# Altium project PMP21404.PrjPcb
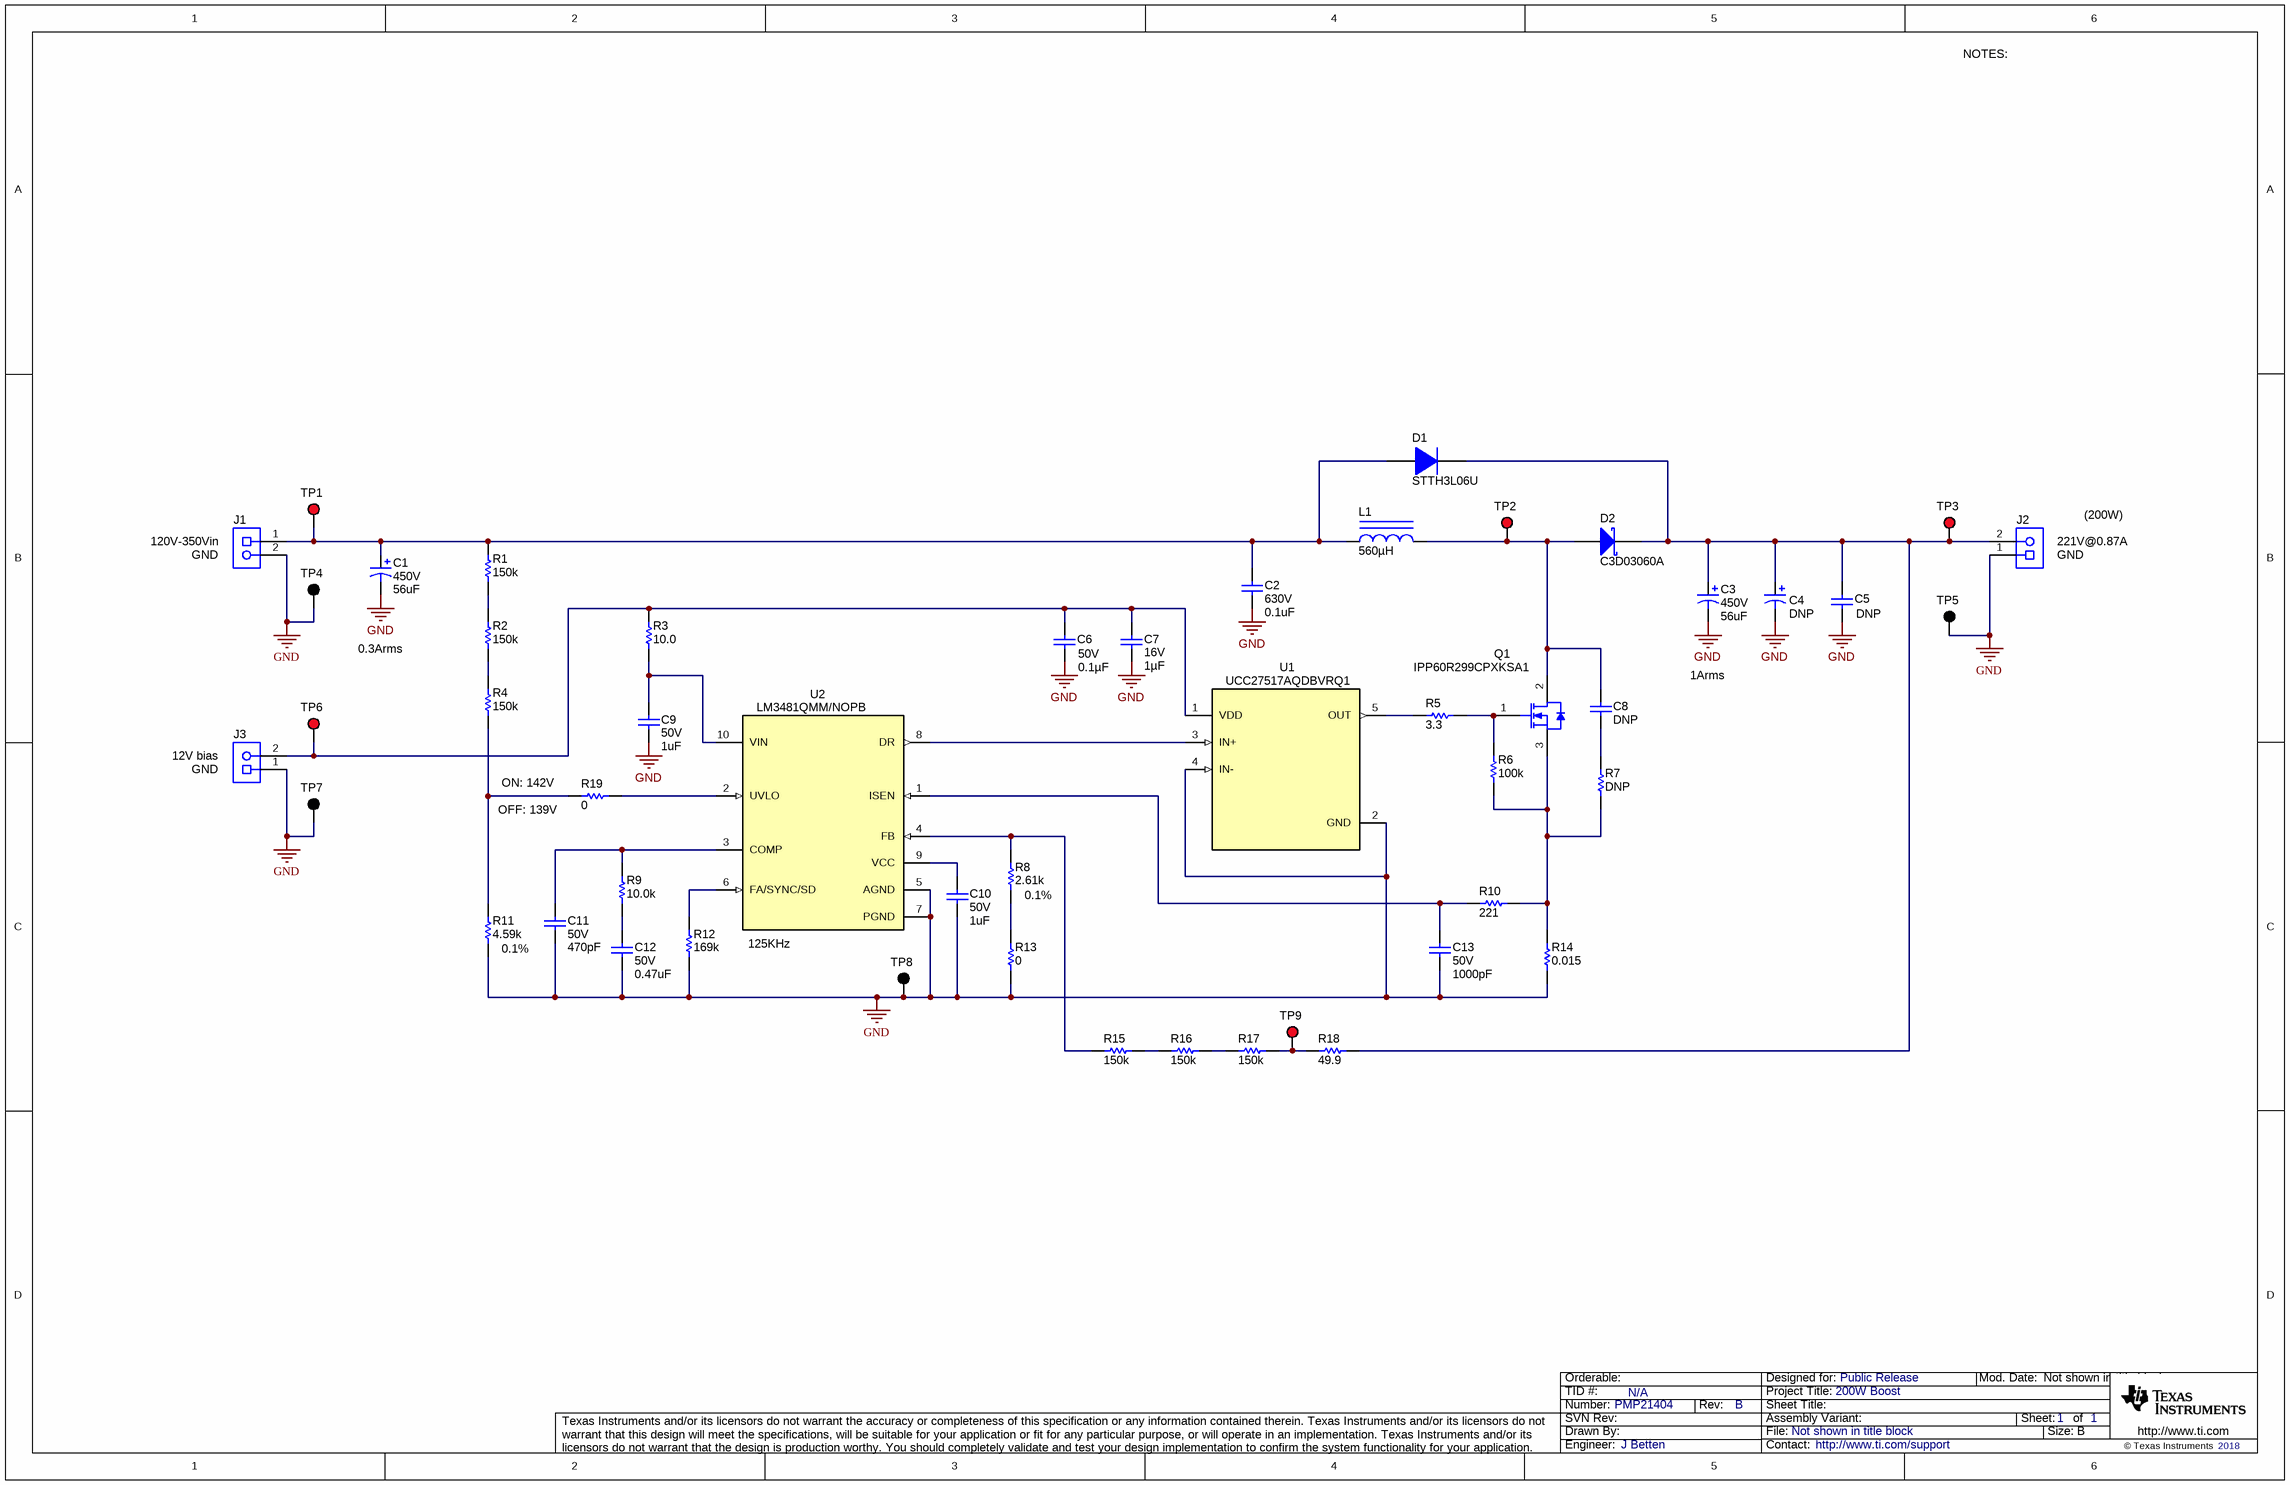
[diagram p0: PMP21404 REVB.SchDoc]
CopyrightYear: 2018; PCB_Layout: J Betten; PCB_Rev: B; PRJ_Customer: Public Release; PRJ_Engineer: J Betten; PRJ_Number: PMP21404; PRJ_Title: 200W Boost; SCH_Rev: B; TechSupport: http://www.ti.com/support; TID: N/A
1 sheet, 50 parts. Net scope: global (net labels, ports and power ports of the same name join across sheets).
Board file: PMP21404 REVB.PcbDoc

## Sheet PMP21404 REVB.SchDoc
size 431 x 279 mm; Date: Not shown in title block; ApprovedBy: Not shown in title block; CheckedBy: Not shown in title block; Author: Not shown in title block; CompanyName: Not shown in title block; Engineer: Not shown in title block; Organization: Not shown in title block; Address1: Not shown in title block; Address2: Not shown in title block; Address3: Not shown in title block; Address4: Not shown in title block; DocumentNumber: 1; Revision: Use project parameter SCH_Rev; SheetNumber: 1; SheetTotal: 1; PageSetup: Record=PageOptions¦CenterHorizontal=True¦CenterVertical=True¦PrintScale=1.00¦XCorrection=1.00¦YCorrection=1.00¦PrintKind=0¦BorderSize=5000000¦LeftOffset=0¦BottomOffset=0¦Orientation=2¦PaperLength=1000¦PaperWidth=1000¦Scale=100¦PaperSource=15¦PrintQuality=600¦MediaType=1¦DitherType=10¦PaperKind=Letter¦PrintScaleMode=1

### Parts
C1  VDC_V: 450V  ValueDisplayed: 56uF  [Nichicon_2000x2500_Snap]  (hidden comment: LLS2W560MELY)
C2  VDC_V: 630V  ValueDisplayed: 0.1uF  [1210_200]  (hidden comment: CGA6L1X7T2J104K160AC)
C3  VDC_V: 450V  ValueDisplayed: 56uF  [Nichicon_2000x2500_Snap]  (hidden comment: LLS2W560MELY)
C4  ValueDisplayed: DNP  [Nichicon_2000x2500_Snap]
C5  ValueDisplayed: DNP  [1210_200]  (hidden comment: CGA6L1X7T2J104K160AC)
C6  VDC_V: 50V  ValueDisplayed: 0.1µF  [0603]  (hidden comment: C0603C104K5RACAUTO)
C7  VDC_V: 16V  ValueDisplayed: 1µF  [0603]  (hidden comment: CGA3E1X7R1C105K080AC)
C8  ValueDisplayed: DNP  [1206_190]  (hidden comment: C3216C0G2E153J160AA)
C9  VDC_V: 50V  ValueDisplayed: 1uF  [0805_HV]  (hidden comment: CGA4J3X7R1H105K125AB)
C10  VDC_V: 50V  ValueDisplayed: 1uF  [0805_HV]  (hidden comment: CGA4J3X7R1H105K125AB)
C11  VDC_V: 50V  ValueDisplayed: 470pF  [0603]  (hidden comment: GRM188R71H471KA01D)
C12  VDC_V: 50V  ValueDisplayed: 0.47uF  [0603]  (hidden comment: CGA3E3X7R1H474K080AB)
C13  VDC_V: 50V  ValueDisplayed: 1000pF  [0603]  (hidden comment: GRM188R71H102JA01D)
D1  STTH3L06U  [SMB]
D2  C3D03060A  [TO-220-2]
J1  Receptacle_2x1  [TERM_BLK_ED555-2DS]  (value not drawn)
J2  Receptacle_2x1  [TERM_BLK_ED555-2DS]  (value not drawn)
J3  Receptacle_2x1  [TERM_BLK_ED555-2DS]  (value not drawn)
L1  ValueDisplayed: 560µH  [Renco_RL1256-3_Pitch_750]  (hidden comment: RL-1256-3-470)
Q1  IPP60R299CPXKSA1  [TO-220AB]
R1  ValueDisplayed: 150k  [1206]  (hidden comment: CRCW1206150KFKEA)
R2  ValueDisplayed: 150k  [1206]  (hidden comment: CRCW1206150KFKEA)
R3  ValueDisplayed: 10.0  [0603]  (hidden comment: CRCW060310R0FKEA)
R4  ValueDisplayed: 150k  [1206]  (hidden comment: CRCW1206150KFKEA)
R5  ValueDisplayed: 3.3  [0603]  (hidden comment: CRCW06033R30JNEA)
R6  ValueDisplayed: 100k  [0603]  (hidden comment: CRCW0603100KFKEA)
R7  ValueDisplayed: DNP  [1206]  (hidden comment: CRCW1206150KFKEA)
R8  Value1: 0.1%  ValueDisplayed: 2.61k  [0603]  (hidden comment: RG1608P-2611-B-T5)
R9  ValueDisplayed: 10.0k  [0603]  (hidden comment: CRCW060310K0FKEA)
R10  value 221  [0603]  (hidden comment: Resistor)
R11  Tolerance_%: 0.1%  ValueDisplayed: 4.59k  [0603]  (hidden comment: RT0603BRD074K59L)
R12  ValueDisplayed: 169k  [0603]  (hidden comment: CRCW0603169KFKEA)
R13  ValueDisplayed: 0  [0603]  (hidden comment: RMCF0603ZT0R00)
R14  ValueDisplayed: 0.015  [1206]  (hidden comment: WSLP1206R0150FEA)
R15  ValueDisplayed: 150k  [1206]  (hidden comment: CRCW1206150KFKEA)
R16  ValueDisplayed: 150k  [1206]  (hidden comment: CRCW1206150KFKEA)
R17  ValueDisplayed: 150k  [1206]  (hidden comment: CRCW1206150KFKEA)
R18  value 49.9  [0603]  (hidden comment: Resistor)
R19  ValueDisplayed: 0  [0603]  (hidden comment: RMCF0603ZT0R00)
TP1  5000  [Keystone5000]  (value not drawn)
TP2  5000  [Keystone5000]  (value not drawn)
TP3  5000  [Keystone5000]  (value not drawn)
TP4  5001  [Keystone5001]  (value not drawn)
TP5  5001  [Keystone5001]  (value not drawn)
TP6  5000  [Keystone5000]  (value not drawn)
TP7  5001  [Keystone5001]  (value not drawn)
TP8  5001  [Keystone5001]  (value not drawn)
TP9  5000  [Keystone5000]  (value not drawn)
U1  UCC27517AQDBVRQ1  [DBV0005A_N]
U2  LM3481QMM/NOPB  [DGS0010A_N]

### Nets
GND: C1.2(-) C2.2 C3.2(-) C4.2(-) C5.2 C6.2 C7.2 C9.2 C10.2 C11.2 C12.2 C13.2 J1.2 J2.1 J3.1 R11.1 R12.1 R13.1 R14.1 TP4.1 TP5.1 TP7.1 TP8.1 U1.2(GND) U1.4(IN-) U2.5(AGND) U2.7(PGND)
NetC1_1: C1.1(+) C2.1 D1.2(A) J1.1 L1.1 R1.2 TP1.1
NetC3_1: C3.1(+) C4.1(+) C5.1 D1.1(K) D2.1(K) J2.2 R18.1 TP3.1
NetC6_1: C6.1 C7.1 J3.2 R3.1 TP6.1 U1.1(VDD)
NetC8_1: C8.1 D2.2(A) L1.2 Q1.2(D) TP2.1
NetC8_2: C8.2 R7.1
NetC9_1: C9.1 R3.2 U2.10(VIN)
NetC10_1: C10.1 U2.9(VCC)
NetC11_1: C11.1 R9.2 U2.3(COMP)
NetC12_1: C12.1 R9.1
NetC13_1: C13.1 R10.2 U2.1(ISEN)
NetQ1_1: Q1.1(G) R5.2 R6.2
NetQ1_3: Q1.3(S) R6.1 R7.2 R10.1 R14.2
NetR1_1: R1.1 R2.2
NetR2_1: R2.1 R4.2
NetR4_1: R4.1 R11.2 R19.2
NetR5_1: R5.1 U1.5(OUT)
NetR8_1: R8.1 R13.2
NetR8_2: R8.2 R15.2 U2.4(FB)
NetR12_2: R12.2 U2.6(FA/SYNC/SD)
NetR15_1: R15.1 R16.2
NetR16_1: R16.1 R17.2
NetR17_1: R17.1 R18.2 TP9.1
NetR19_1: R19.1 U2.2(UVLO)
NetU1_3: U1.3(IN+) U2.8(DR)

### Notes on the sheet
- NOTES:
- (near J1) 120V-350Vin
- (near J1) GND
- (near J2) 221V@0.87A
- (near J2) GND
- (200W)
- 0.3Arms
- 1Arms
- (near J3) 12V bias
- (near J3) GND
- (near R19) ON: 142V
- (near R19) OFF: 139V
- (near U2) 125KHz

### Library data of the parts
C1 C3 = CMP-0010119-2: CAP, AL, 56 uF, 450 V, +/- 20%, TH; Manufacturer: Nichicon; TaMin_C: -25°C; Polarized: Y; SizeAreaWB_mm2: 484; Value1: Unknown; U/M: EA; Value: 56uF; TaMax_C: 85°C; SizeZ_mm: 27; SizeX_mm: 20; Cap_Case: 20x25mm; SizeArea_mm2: 400; CompType: Capacitor; AEC Qualified: N; Cap_F: 56µF; IRMS_A: 6.1dA; AEC Category: Q200
C2 = CMP-0009140-2: CAP, CERM, 0.1 uF, 630 V, +/- 10%, X7R, AEC-Q200 Grade 1, 1210; Manufacturer: TDK; TaMin_C: -55°C; Polarized: N; SizeAreaWB_mm2: 14.7; Value1: Unknown; U/M: EA; Value: 0.1uF; TaMax_C: 125°C; SizeZ_mm: 2; SizeX_mm: 3.2; SizeY_mm: 2.5; Cap_Case: 1210; SizeArea_mm2: 8; AEC Qualified: Y; Cap_F: 100nF; AEC Grade: 1; AEC Category: Q200
C4 = CMP-0010119-2: CAP, AL, DNP; TaMin_C: -25°C; Polarized: Y; SizeAreaWB_mm2: 484; Value1: Unknown; U/M: EA; TaMax_C: 85°C; Tolerance_%: 20%; SizeZ_mm: 27; SizeX_mm: 20; Cap_Case: 20x25mm; SizeArea_mm2: 400; CompType: Capacitor; AEC Qualified: N; AEC Category: Q200
C5 = CMP-0009140-2: CAP, CERM, DNP; Polarized: N; SizeAreaWB_mm2: 14.7; Value1: Unknown; U/M: EA; SizeZ_mm: 2; SizeX_mm: 3.2; SizeY_mm: 2.5; Cap_Case: 1210; SizeArea_mm2: 8; CompType: Capacitor; AEC Qualified: Y; AEC Grade: 1; AEC Category: Q200
C6 = CMP-0079602-1: CAP, CERM, 0.1 µF, 50 V,+/- 10%, X7R, AEC-Q200 Grade 1, 0603; Manufacturer: Kemet; TaMin_C: -55°C; Polarized: N; SizeAreaWB_mm2: 4.68; U/M: EA; Value: 0.1uF; TaMax_C: 125°C; SizeZ_mm: 1; SizeX_mm: 1.6; SizeY_mm: 0.8; SizeArea_mm2: 1.28; CompType: Capacitor; AEC Qualified: Y; Cap_F: 100nF; AEC Category: Q200
C7 = CMP-0079607-1: CAP, CERM, 1 µF, 16 V,+/- 10%, X7R, AEC-Q200 Grade 1, 0603; Manufacturer: TDK; TaMin_C: -55°C; Polarized: N; SizeAreaWB_mm2: 4.68; U/M: EA; Value: 1uF; TaMax_C: 125°C; SizeZ_mm: 1; SizeX_mm: 1.6; SizeY_mm: 0.8; SizeArea_mm2: 1.28; AEC Qualified: Y; AEC Category: Q200
C8 = CMP-0008644-2: CAP, CERM, DNP; Polarized: N; SizeAreaWB_mm2: 10.92; Value1: Unknown; U/M: EA; SizeZ_mm: 1.9; SizeX_mm: 3.2; SizeY_mm: 1.6; Cap_Case: 1206; SizeArea_mm2: 5.12; CompType: Capacitor; AEC Category: Q200
C9 C10 = CMP-0007976-2: CAP, CERM, 1 uF, 50 V, +/- 10%, X7R, AEC-Q200 Grade 1, 0805; Manufacturer: TDK; TaMin_C: -55°C; ESR_ohm: 8.782m; Polarized: N; SizeAreaWB_mm2: 6.75; Value1: 0.008782 ohm; U/M: EA; Value: 1uF; TaMax_C: 125°C; SizeZ_mm: 1.45; SizeX_mm: 2; SizeY_mm: 1.25; Cap_Case: 0805; SizeArea_mm2: 2.5; AEC Qualified: Y; Cap_F: 1µF; IRMS_A: 2.20488A; AEC Grade: 1; AEC Category: Q200
C11 = CMP-0007455-4: CAP, CERM, 470 pF, 50 V, +/- 10%, X7R, 0603; Manufacturer: MuRata; TaMin_C: -55°C; Polarized: N; SizeAreaWB_mm2: 4.68; Value1: Unknown; U/M: EA; Value: 470pF; TaMax_C: 125°C; SizeZ_mm: 1; SizeX_mm: 1.6; SizeY_mm: 0.8; SizeArea_mm2: 1.28; AEC Category: Q200
C12 = CMP-0007096-4: CAP, CERM, 0.47 uF, 50 V, +/- 10%, X7R, AEC-Q200 Grade 1, 0603; Manufacturer: TDK; TaMin_C: -55°C; ESR_ohm: 0.01064; Polarized: N; SizeAreaWB_mm2: 4.68; Value1: 0.01064 ohm; U/M: EA; Value: 0.47uF; TaMax_C: 125°C; SizeZ_mm: 1; SizeX_mm: 1.6; SizeY_mm: 0.8; SizeArea_mm2: 1.28; AEC Qualified: Y; Cap_F: 470nF; IRMS_A: 1.59966A; AEC Category: Q200
C13 = CMP-0007431-4: CAP, CERM, 1000 pF, 50 V, +/- 5%, X7R, 0603; Manufacturer: MuRata; TaMin_C: -55°C; Polarized: N; SizeAreaWB_mm2: 4.68; Value1: Unknown; U/M: EA; Value: 1000pF; TaMax_C: 125°C; SizeZ_mm: 1; SizeX_mm: 1.6; SizeY_mm: 0.8; SizeArea_mm2: 1.28; Cap_F: 1nF; AEC Category: Q200
D1 = CMP-0077014-1: Diode, Ultrafast, 600 V, 3 A, SMB; Manufacturer: STMicroelectronics; SizeAreaWB_mm2: 44.156; Vr_V: 600V; SizeArea_mm2: 21.336; TJmax_C: 175°C; AEC Category: Q101; Value: 600V; SizeZ_mm: 2.6; Green_REACh: Incomplete; Io_A: 3A; Vf_V: 1.3V; SizeY_mm: 3.81; Green_Lifecycle: Not Set; U/M: EA; SizeX_mm: 5.6
D2 = CMP-0079543-1: Diode, Schottky, 600 V, 11 A, AEC-Q101, TH; Manufacturer: Cree; SizeAreaWB_mm2: 77.630025; Vr_V: 600V; SizeArea_mm2: 44.650025; AEC Qualified: Y; TJmax_C: 175°C; AEC Category: Q101; Value: 600V; SizeZ_mm: 20; Green_REACh: Incomplete; Io_A: 11A; SizeY_mm: 4.445; Green_Lifecycle: Active; SizeX_mm: 10.045; RJC_CperW: 3.2
J1-J3 = CMP-0074913-1: Terminal Block, 3.5mm Pitch, 2x1, TH; PartNumber: ED555/2DS; Manufacturer: On-Shore Technology; Cert_CULUS: Y; CNHeader: False; ContactFinish: Brass; CT: True; Current_A: 6A; Gender: Female; Green_Lifecycle: Active; Green_REACh: Passed; Pitch_mm: 3.5; Row_Count: 1; Shrouded: N; Voltage_V: 150V
L1 = CMP-0077831-1: Inductor, 560 µH, 2.6 A, 0.270 ohm, TH; PartNumber: PCV-2-564-02L; Manufacturer: Coilcraft; SizeAreaWB_mm2: 896.4036; SizeArea_mm2: 780.6436; AEC Qualified: N; AEC Category: Q200; Value: 560uH; SizeZ_mm: 21.59; SizeY_mm: 27.94; Value2: 2.6A; DCR_ohm: 1.87d
Q1 = CMP-0001176-3: MOSFET, N-CH, 600 V, 11 A, TO-220AB; Alternate Manufacturer: None; Manufacturer: Infineon Technologies; SizeZ_mm: 19.4; ChType: N; Value2: 22 nC; VdsMax_V: 600V; SizeX_mm: 10.2; SizeY_mm: 4.5; Vgs_V: 20V; Value: 600V; SizeArea_mm2: 45.9; AEC Category: Q101; IdsMax_A: 11A; SizeAreaWB_mm2: 79.3; U/M: EA; QgTyp_nC: 22
R1 R2 R4 R15-R17 = CMP-0016639-3: RES, 150 k, 1%, 0.25 W, AEC-Q200 Grade 0, 1206; Manufacturer: Vishay-Dale; Power_W: 250mW; TempCo: 100 ppm/C; Value: 150k; EIA_Code: E96; SizeX_mm: 3.2; SizeY_mm: 1.6; SizeZ_mm: 1.35; Value2: 0.25W; SizeArea_mm2: 5.12; AEC Qualified: Y; VDC_V: 200V; AEC Category: Q200; AEC Grade: 0
R3 = CMP-0022003-4: RES, 10.0, 1%, 0.1 W, AEC-Q200 Grade 0, 0603; Manufacturer: Vishay-Dale; Power_W: 100mW; TempCo: 100 ppm/C; Value_Code: 10R0; Value: 10.0; EIA_Code: E96; Res_ohm: 10; SizeX_mm: 1.6; SizeY_mm: 0.8; SizeZ_mm: 1; Value2: 0.1W; SizeArea_mm2: 1.28; AEC Qualified: Y; VDC_V: 75V; AEC Category: Q200; AEC Grade: 0
R5 = CMP-0025805-4: RES, 3.3, 5%, 0.1 W, AEC-Q200 Grade 0, 0603; Manufacturer: Vishay-Dale; Power_W: 100mW; TempCo: 200 ppm/C; Value_Code: 3R30; Value: 3.3; EIA_Code: E24; SizeX_mm: 1.6; SizeY_mm: 0.8; SizeZ_mm: 1; Value2: 0.1W; SizeArea_mm2: 1.28; AEC Qualified: Y; VDC_V: 75V; AEC Category: Q200; AEC Grade: 0
R6 = CMP-0021990-4: RES, 100 k, 1%, 0.1 W, AEC-Q200 Grade 0, 0603; Manufacturer: Vishay-Dale; Power_W: 100mW; TempCo: 100 ppm/C; Value: 100k; EIA_Code: E96; SizeX_mm: 1.6; SizeY_mm: 0.8; SizeZ_mm: 1; Value2: 0.1W; SizeArea_mm2: 1.28; AEC Qualified: Y; VDC_V: 75V; AEC Category: Q200; AEC Grade: 0
R7 = CMP-0016639-3: RES, DNP, 1206; TempCo: 100 ppm/C; EIA_Code: E96; SizeX_mm: 3.2; SizeY_mm: 1.6; SizeZ_mm: 1.35; SizeArea_mm2: 5.12; CompType: Resistor; AEC Qualified: Y; AEC Category: Q200; AEC Grade: 0
R8 = CMP-0023494-3: RES, 2.61 k, 0.1%, 0.1 W, 0603; Manufacturer: Susumu Co Ltd; Power_W: 100mW; TempCo: 25 ppm/C; Value_Code: 2k61; U/M: EA; Value: 2.61k; EIA_Code: E192; SizeX_mm: 1.6; SizeY_mm: 0.8; SizeZ_mm: 1; Value2: 0.1W; SizeArea_mm2: 1.28; CompType: Resistor; VDC_V: 75V; AEC Category: Q200
R9 = CMP-0021998-4: RES, 10.0 k, 1%, 0.1 W, AEC-Q200 Grade 0, 0603; Manufacturer: Vishay-Dale; Power_W: 100mW; TempCo: 100 ppm/C; Value_Code: 10k0; Value: 10.0k; EIA_Code: E96; Res_ohm: 10k; SizeX_mm: 1.6; SizeY_mm: 0.8; SizeZ_mm: 1; Value2: 0.1W; SizeArea_mm2: 1.28; AEC Qualified: Y; VDC_V: 75V; AEC Category: Q200; AEC Grade: 0
R10 = CMP-0022217-5: RES, 221, 1%, 0.1 W, AEC-Q200 Grade 0, 0603; PartNumber: CRCW0603221RFKEA; Manufacturer: Vishay-Dale; Value_Code: 221R; Power_W: 100mW; Value2: 0.1W; VDC_V: 75V; TempCo: 100 ppm/C; EIA_Code: E96; AEC Category: Q200; AEC Grade: 0; AEC Qualified: Y; SizeArea_mm2: 1.28; SizeX_mm: 1.6; SizeY_mm: 0.8; SizeZ_mm: 1
R11 = CMP-0024297-2: RES, 4.59 k, 0.1%, 0.1 W, 0603; Manufacturer: Yageo America; Power_W: 100mW; TempCo: 25 ppm/C; Value_Code: 4k59; U/M: EA; Value: 4.59k; EIA_Code: E192; SizeX_mm: 1.6; SizeY_mm: 0.8; SizeZ_mm: 1; Value2: 0.1W; SizeArea_mm2: 1.28; CompType: Resistor; VDC_V: 75V; AEC Category: Q200
R12 = CMP-0022077-4: RES, 169 k, 1%, 0.1 W, AEC-Q200 Grade 0, 0603; Manufacturer: Vishay-Dale; Power_W: 100mW; TempCo: 100 ppm/C; Value: 169k; EIA_Code: E96; SizeX_mm: 1.6; SizeY_mm: 0.8; SizeZ_mm: 1; Value2: 0.1W; SizeArea_mm2: 1.28; AEC Qualified: Y; VDC_V: 75V; AEC Category: Q200; AEC Grade: 0
R13 R19 = CMP-0023343-3: RES, 0, 1%, 0.1 W, AEC-Q200 Grade 0, 0603; Manufacturer: Stackpole Electronics Inc; Power_W: 100mW; TempCo: ppm/C; U/M: EA; Value: 0; SizeX_mm: 1.6; SizeY_mm: 0.8; SizeZ_mm: 1; Value2: 0.1W; SizeArea_mm2: 1.28; CompType: Resistor; AEC Qualified: Y; AEC Category: Q200
R14 = CMP-0018571-2: RES, 0.015, 1%, 1 W, 1206; Manufacturer: Vishay-Dale; Power_W: 1W; TempCo: 75 ppm/C; Value_Code: R015; U/M: EA; Value: 0.015; EIA_Code: E96; SizeX_mm: 3.2; SizeY_mm: 1.6; SizeZ_mm: 1.35; SizeArea_mm2: 5.12; AEC Category: Q200
R18 = CMP-0022448-4: RES, 49.9, 1%, 0.1 W, AEC-Q200 Grade 0, 0603; PartNumber: CRCW060349R9FKEA; Manufacturer: Vishay-Dale; Value_Code: 49R9; Power_W: 100mW; Value2: 0.1W; VDC_V: 75V; TempCo: 100 ppm/C; EIA_Code: E96; AEC Category: Q200; AEC Grade: 0; AEC Qualified: Y; SizeArea_mm2: 1.28; SizeX_mm: 1.6; SizeY_mm: 0.8; SizeZ_mm: 1
TP1-TP3 TP6 TP9 = CMP-0055137-1: Test Point, Miniature, Red, TH; Manufacturer: Keystone; CNHeader: FALSE; ContactFinish: Silver; CT: TRUE; Green_Lifecycle: Active; Green_REACh: Passed
TP4 TP5 TP7 TP8 = CMP-0055138-1: Test Point, Miniature, Black, TH; Manufacturer: Keystone; CNHeader: FALSE; ContactFinish: Silver; CT: TRUE; Green_Lifecycle: Active; Green_REACh: Passed
U1 = CMP-0066947-1: 4A/4A Single Channel High-speed Low-side Gate Driver, DBV0005A (SOT-23-5); Alternate Manufacturer: Texas Instruments; Green_Lifecycle: Active; SizeAreaWB_mm2: 14.82; Green_REACh: Passed; U/M: EA; SizeZ_mm: 1.45; SizeX_mm: 2.8; SizeY_mm: 2.9; SizeArea_mm2: 8.12; CompType: IC
U2 = CMP-0071928-2: High Efficiency Low-Side N-Channel Controller for Switching Regulators, AEC-Q100 Grade 1, 10-pin Mini SOIC, 1000 Reel; Manufacturer: Texas Instruments; Alternate PartNumber: LM3481QMMX/NOPB; CompType: IC; AEC Category: Q200; AEC Qualified: Y; SizeAreaWB_mm2: 23.6; SizeArea_mm2: 14.7; SizeX_mm: 4.9; SizeY_mm: 3; SizeZ_mm: 1.1

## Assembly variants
001: all parts fitted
